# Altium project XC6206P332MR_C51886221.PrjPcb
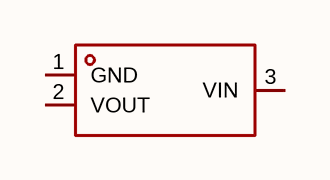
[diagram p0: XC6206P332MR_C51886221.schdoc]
1 sheet, 1 parts. Net scope: global (net labels, ports and power ports of the same name join across sheets).

## Sheet XC6206P332MR_C51886221.schdoc
size 127 x 101 mm

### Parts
U?  xc6206p332mr_c51886221  [SOT-23-3_L2.9-W1.6-P1.90-LS2.8-BR]  (value not drawn)

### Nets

Not connected (* = marked no-connect by the designer): U? 1(GND) 2(VOUT) 3(VIN)

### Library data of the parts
U? = xc6206p332mr_c51886221: 输出极性:正极;工作电压:6V;输出电压:3.3V;输出电流:100mA;电源纹波抑制比(PSRR):45dB@(1kHz);输出类型:固定;; Manufacturer: TECH PUBLIC(台舟); AddInBom: yes; ModelId: 89cb27a44ab2466697082bb9fd73a7d0; ModelName: SOT-23-3L_L2.9-W1.6-H1.1-LS2.8-P0.95; ModelTransform: 114.173,110.236,0,90,0,0,0,0,0; Output Configuration: 正极; Voltage - Supply: 6V; Output Voltage: 3.3V; Output Current: 100mA; Voltage Dropout: 160mV@(50mA); standby current: 6uA; Output Type: 固定; Number of Outputs: 1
